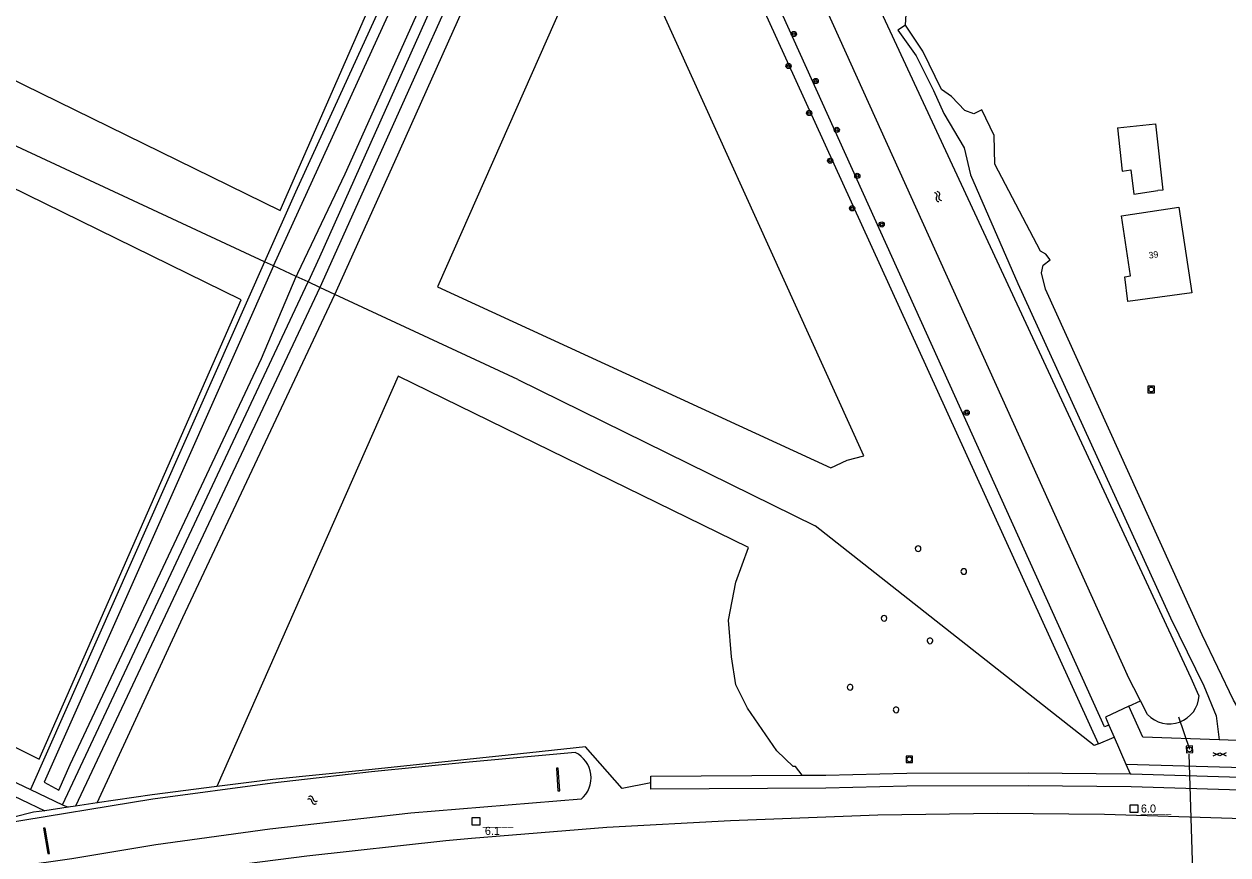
# Model space of a CAD drawing. Extents: x 133000 to 136000, y 400500 to 403500.
# Drawn here: x 133961.7 to 134147.3, y 401178.4 to 401306.4 of the extents above; entities that cross this region are included whole.
import ezdxf

# ---------------------------------------------------------------- set-up
doc = ezdxf.new("R2010")
doc.units = 0
for name, color, linetype in [('gg-afsc-hekwerk', 7, 'Continuous'), ('gg-anno-huisnummerreeks BGT', 7, 'Continuous'), ('gg-bbg-bijgebouw', 7, 'Continuous'), ('gg-bbg-gedigitaliseerde bebouwing', 7, 'Continuous'), ('gg-bbg-gedigitaliseerde bijgebouw', 7, 'Continuous'), ('gg-bbg-hoofdgebouw', 7, 'Continuous'), ('gg-bbg-hoogspanningsmast', 7, 'Continuous'), ('gg-knt-verharding', 7, 'Continuous'), ('gg-kntw-bovenkant insteek waterloop', 7, 'Continuous'), ('gg-kwrk-duiker nz buis', 7, 'Continuous'), ('gg-kwrk-kunstwerk', 7, 'Continuous'), ('gt-anno-nummer hm paal', 7, 'Continuous'), ('gt-grn-groengrens', 7, 'Continuous'), ('gt-grn-vlakafsluiter', 7, 'Continuous'), ('gt-symb-boom', 7, 'Continuous'), ('gt-symb-gesloten verharding', 7, 'Continuous'), ('gt-symb-hm paal', 7, 'Continuous'), ('gt-symb-rioolschacht', 7, 'Continuous'), ('gt-symb-watersymbool', 7, 'Continuous')]:
    doc.layers.add(name, color=color, linetype=linetype)

# ---------------------------------------------------------------- blocks, each defined once
blk = doc.blocks.new('gt0-RS')
at = {"layer": 'gt-symb-rioolschacht'}
blk.add_lwpolyline([(-0.5, -0.5), (0.5, -0.5), (0.5, 0.5), (-0.5, 0.5)], close=True, dxfattribs=at)
blk.add_circle((0, 0), 0.375, dxfattribs=at)
blk = doc.blocks.new('gt0-GESVH1')
at = {"layer": 'gt-symb-gesloten verharding'}
for p, q in [((-0.99, -0.26), (0.01, 0.24)), ((0.01, -0.26), (-0.99, 0.24)), ((0.01, 0.24), (1.01, -0.26)), ((1.01, 0.24), (0.01, -0.26))]:
    blk.add_line(p, q, dxfattribs=at)
blk = doc.blocks.new('gt0-BOOM')
at = {"layer": 'gt-symb-boom'}
for radius in [0.4, 0.2]:
    blk.add_circle((0, 0), radius, dxfattribs=at)
blk = doc.blocks.new('gt0-WA')
at = {"layer": 'gt-symb-watersymbool'}
for centre, start, end in [((-0.32, 0.02), 28.0725, 151.9275), ((0.43, 0.42), 208.0725, 331.9275), ((-0.32, -0.43), 28.0725, 151.9275), ((0.43, -0.03), 208.0725, 331.9275)]:
    blk.add_arc(centre, 0.425, start, end, dxfattribs=at)
blk = doc.blocks.new('gt0-HMpaal')
at = {"layer": 'gt-symb-hm paal'}
blk.add_lwpolyline([(-0.6, 0.6), (0.6, 0.6), (0.6, -0.6), (-0.6, -0.6)], close=True, dxfattribs=at)

msp = doc.modelspace()

# ---------------------------------------------------------------- linework, layer by layer
at = {"layer": 'gg-afsc-hekwerk'}
for p, q in [((133969.63, 401185.95), (133968.5, 401185.78)), ((133973, 401186.45), (133969.63, 401185.95)), ((133968.5, 401185.78), (133964.93, 401185.25))]:
    msp.add_line(p, q, dxfattribs=at)
for points in [[(134048.24, 401195.11), (134036.33, 401193.83), (134015.35, 401191.62), (134000.05, 401190.07), (133991.45, 401188.98)], [(134058.31, 401189.55), (134053.89, 401188.66), (134048.24, 401195.11)], [(133991.45, 401188.98), (133981.49, 401187.71), (133973, 401186.45)], [(133964.93, 401185.25), (133963.2, 401185), (133957.08, 401183.46)]]:
    msp.add_lwpolyline(points, dxfattribs=at)
at = {"layer": 'gg-bbg-bijgebouw'}
msp.add_lwpolyline([(134130.25, 401290.43), (134130.98, 401283.79), (134132.27, 401283.99), (134132.78, 401280.23), (134136.46, 401280.77)], dxfattribs=at)
at = {"layer": 'gg-bbg-gedigitaliseerde bebouwing'}
msp.add_lwpolyline([(134130.87, 401276.91), (134139.71, 401278.23), (134141.69, 401265.03), (134131.84, 401263.67)], dxfattribs=at)
at = {"layer": 'gg-bbg-gedigitaliseerde bijgebouw'}
msp.add_lwpolyline([(134130.25, 401290.43), (134136.12, 401291.07), (134137.24, 401280.86), (134136.46, 401280.77)], dxfattribs=at)
at = {"layer": 'gg-bbg-hoofdgebouw'}
msp.add_lwpolyline([(134131.84, 401263.67), (134131.36, 401267.52), (134132.26, 401267.65), (134130.87, 401276.91)], dxfattribs=at)
at = {"layer": 'gg-bbg-hoogspanningsmast'}
for centre, start, end in [((134099.51, 401225.63), 0, 180), ((134099.51, 401225.63), 180, 0), ((134106.55, 401222.1), 0, 180), ((134106.55, 401222.1), 180, 0), ((134094.26, 401214.89), 0, 180), ((134094.26, 401214.89), 180, 0), ((134101.34, 401211.41), 0.1332, 180.2656), ((134101.34, 401211.41), 180.2661, 0.1327), ((134089.03, 401204.27), 0.1332, 180.2656), ((134089.03, 401204.27), 180.2661, 0.1327), ((134096.11, 401200.78), 0.1327, 180.2661), ((134096.11, 401200.78), 180.2656, 0.1332)]:
    msp.add_arc(centre, 0.431, start, end, dxfattribs=at)
at = {"layer": 'gg-knt-verharding'}
for p, q in [((134128.92, 401198.42), (134129.74, 401196.56)), ((134129.74, 401196.56), (134131.54, 401192.42)), ((134152.86, 401195.92), (134145.91, 401196.16)), ((134131.54, 401192.42), (134152.8, 401191.81))]:
    msp.add_line(p, q, dxfattribs=at)
for points in [[(134097.58, 401306.29), (134096.38, 401305.49), (134099.2, 401301.54), (134101.86, 401296.21), (134103.48, 401292.66), (134106.59, 401287.38), (134107.59, 401283.19), (134114.87, 401266.48), (134138.4, 401214.98), (134143.52, 401204.5), (134145.43, 401199.87), (134145.91, 401196.16)], [(134152.86, 401195.92), (134150.48, 401198.29), (134148.1, 401202.3), (134143.3, 401212.36), (134119.14, 401265.57), (134118.55, 401268.13), (134118.76, 401269.27), (134119.85, 401270.1), (134119.18, 401270.99), (134118.39, 401271.43), (134111.35, 401284.83), (134111.23, 401289.28), (134109.35, 401293.24), (134108.08, 401292.59), (134106.72, 401293.11), (134104.66, 401295.27), (134103.1, 401296.34), (134100.24, 401302.25), (134097.58, 401306.29)], [(134131.97, 401201.34), (134128.38, 401199.66), (134128.92, 401198.42)], [(134145.91, 401196.16), (134134.14, 401196.56), (134131.97, 401201.34)], [(133846.84, 401144.85), (133876.76, 401153.5), (133898.49, 401159.1), (133919.96, 401164), (133941.47, 401168.4), (133963.14, 401172.3), (133983.98, 401175.59), (134005.29, 401178.31), (134026.74, 401180.66), (134030.7, 401181.03), (134051.53, 401182.71), (134070.59, 401183.72), (134093.28, 401184.63), (134111.76, 401184.85), (134128.22, 401184.7), (134147.89, 401184.12), (134156.18, 401183.82)]]:
    msp.add_lwpolyline(points, dxfattribs=at)
at = {"layer": 'gg-kntw-bovenkant insteek waterloop'}
for p, q in [((134141.58, 401205.66), (134075.06, 401348.61)), ((134068.77, 401345.42), (134131.73, 401206.19)), ((134133.79, 401202.19), (134131.73, 401206.19)), ((134142.8, 401203.01), (134141.58, 401205.66)), ((134134.87, 401200.09), (134133.79, 401202.19))]:
    msp.add_line(p, q, dxfattribs=at)
for points in [[(134046.68, 401194.2), (134029.74, 401192.7), (134015.25, 401191.25), (134000.03, 401189.5), (133981.58, 401187.03), (133958.42, 401183.24)], [(134047.57, 401187.03), (134021.33, 401184.85), (133999.62, 401182.43), (133982.02, 401180.01), (133969.11, 401177.84), (133960.75, 401176.67)]]:
    msp.add_lwpolyline(points, dxfattribs=at)
for centre, radius, start, end in [((134138.23, 401203.2), 4.58, 222.8427, 357.5789), ((134044.81, 401190.33), 4.3, 309.8861, 64.2754)]:
    msp.add_arc(centre, radius, start, end, dxfattribs=at)
at = {"layer": 'gg-kwrk-duiker nz buis'}
for p, q in [((134139.65, 401199.69), (134141.33, 401194.71)), ((134141.24, 401193.98), (134142.44, 401155.61))]:
    msp.add_line(p, q, dxfattribs=at)
at = {"layer": 'gg-kwrk-kunstwerk'}
for p, q in [((134058.31, 401190.55), (134081.62, 401190.7)), ((134058.31, 401189.55), (134058.31, 401190.55))]:
    msp.add_line(p, q, dxfattribs=at)
for points in [[(134044.01, 401188.3), (134044.27, 401188.32), (134044.05, 401191.81), (134043.8, 401191.8), (134044.01, 401188.3)], [(134081.62, 401190.7), (134085.3, 401190.72), (134097.78, 401191.01), (134116.49, 401191.09), (134132.19, 401190.93)], [(134132.19, 401190.93), (134132.35, 401190.93), (134154.21, 401190.28), (134191.91, 401188.24), (134196.02, 401189.38)], [(134196.96, 401187.65), (134191.91, 401186.24), (134154.21, 401188.28), (134132.35, 401188.93), (134116.49, 401189.09), (134097.78, 401189.01), (134085.3, 401188.72), (134058.31, 401188.55), (134058.31, 401189.55)], [(133964.97, 401182.57), (133964.72, 401182.54), (133965.39, 401178.66), (133965.63, 401178.68), (133964.97, 401182.57)]]:
    msp.add_lwpolyline(points, dxfattribs=at)
at = {"layer": 'gt-grn-groengrens'}
for p, q in [((134127.31, 401195.57), (134057.34, 401348.94)), ((133998.8, 401269.83), (133921.76, 401305.65)), ((133998.8, 401269.83), (133962.7, 401188.52)), ((134000.17, 401269.19), (133998.8, 401269.83)), ((134003.65, 401267.57), (134000.17, 401269.19)), ((134005.49, 401266.71), (134003.65, 401267.57)), ((133967.67, 401186.18), (134005.49, 401266.71)), ((134007.32, 401265.86), (133969.63, 401185.95)), ((134007.32, 401265.86), (134005.49, 401266.71)), ((134009.62, 401264.79), (134007.32, 401265.86)), ((134037.82, 401251.68), (134009.62, 401264.79)), ((134037.82, 401251.68), (134083.62, 401229.15)), ((134103, 401213.91), (134083.62, 401229.15)), ((133885.56, 401224.96), (133962.7, 401188.52)), ((133884.74, 401223.14), (133964.93, 401185.25)), ((134127.31, 401195.57), (134129.74, 401196.56)), ((133962.7, 401188.52), (133967.67, 401186.18)), ((133967.67, 401186.18), (133968.5, 401185.78))]:
    msp.add_line(p, q, dxfattribs=at)
for points in [[(133935.23, 401309.99), (134001.18, 401277.71), (134034.31, 401353.3), (133967.94, 401383.8), (133935.23, 401309.99)], [(134128.92, 401198.42), (134128.22, 401198.16), (134057.35, 401354.93), (134055.58, 401358.84)], [(134053.02, 401358.43), (134041.12, 401353.19), (134035.75, 401349.71), (134034.48, 401348.03), (134032.46, 401343.76), (134003.56, 401280.56), (133998.8, 401269.83)], [(134000.17, 401269.19), (134035.95, 401347.49), (134036.39, 401348.31), (134041.76, 401351.82), (134053.66, 401357.02)], [(134054.8, 401354.52), (134051.32, 401352.64), (134043.34, 401348.24), (134039.69, 401346.08), (134039.17, 401345.55), (134011.16, 401283.3), (134003.85, 401268.01), (134003.65, 401267.57)], [(134055.42, 401353.17), (134044.14, 401347.19), (134040.55, 401344.73), (134038.86, 401340.77), (134029.02, 401319.21), (134007.27, 401270.51), (134005.49, 401266.71)], [(134056.27, 401351.29), (134042.07, 401343.15), (134007.32, 401265.86)], [(134009.62, 401264.79), (134018.89, 401285.28), (134039.25, 401330.84), (134044.05, 401341.39), (134057.34, 401348.94)], [(134025.46, 401265.93), (134086.06, 401238.08), (134088.59, 401239.23), (134091.17, 401239.9), (134052.05, 401326.12), (134025.46, 401265.93)], [(133964.06, 401193.2), (133995.16, 401263.97), (133929.15, 401296.28), (133898.16, 401226.29), (133964.06, 401193.2)], [(134000.17, 401269.19), (133996.57, 401261.1), (133964.8, 401189.64), (133967.07, 401188.44), (133968.85, 401192.35), (133998.3, 401254.91), (134003.65, 401267.57)], [(133973, 401186.45), (133986.19, 401215.01), (134009.62, 401264.79)], [(134081.62, 401190.7), (134080.59, 401192.04), (134080.25, 401192.04), (134077.74, 401194.49), (134073.23, 401201.04), (134071.42, 401204.66), (134070.74, 401208.95), (134070.29, 401214.6), (134071.42, 401220.47), (134073.35, 401225.8), (134019.4, 401252.21), (133991.45, 401188.98)], [(134127.31, 401195.57), (134126.64, 401195.31), (134103, 401213.91)]]:
    msp.add_lwpolyline(points, dxfattribs=at)
at = {"layer": 'gt-grn-vlakafsluiter'}
for p, q in [((134097.58, 401306.29), (134098.16, 401316.86)), ((134131.97, 401201.34), (134133.79, 401202.19)), ((134131.54, 401192.42), (134132.19, 401190.93))]:
    msp.add_line(p, q, dxfattribs=at)

# ---------------------------------------------------------------- block references
at = {"layer": 'gt-symb-boom'}
for p in [(134080.36, 401304.9), (134079.54, 401299.97), (134083.73, 401297.67), (134082.72, 401292.73), (134086.97, 401290.13), (134085.97, 401285.38), (134090.14, 401283.05), (134089.34, 401278.05), (134093.9, 401275.56), (134107, 401246.57)]:
    msp.add_blockref('gt0-BOOM', p, dxfattribs=at)
at = {"layer": 'gt-symb-gesloten verharding'}
msp.add_blockref('gt0-GESVH1', (134145.98, 401193.95), dxfattribs=at)
at = {"layer": 'gt-symb-hm paal'}
for p in [(134132.77, 401185.57), (134031.37, 401183.62)]:
    msp.add_blockref('gt0-HMpaal', p, dxfattribs=at)
at = {"layer": 'gt-symb-rioolschacht'}
for p in [(134135.44, 401250.14), (134098.16, 401193.16)]:
    msp.add_blockref('gt0-RS', p, dxfattribs=at)
at = {"layer": 'gt-symb-rioolschacht', "rotation": -177.70709950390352}
msp.add_blockref('gt0-RS', (134141.33, 401194.71), dxfattribs=at)
at = {"layer": 'gt-symb-watersymbool'}
for p, rotation in [((134102.55, 401279.91), -64.8446275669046), ((134006.13, 401186.9), -24.131125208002)]:
    msp.add_blockref('gt0-WA', p, dxfattribs=dict(at, rotation=rotation))

# ---------------------------------------------------------------- texts
at = {"layer": 'gg-anno-huisnummerreeks BGT'}
msp.add_text('39', height=1, rotation=8.5, dxfattribs=at).set_placement((134135.12, 401270.29))
at = {"layer": 'gt-anno-nummer hm paal'}
for s, p in [('6.0', (134133.85, 401184.96)), ('6.1', (134032.74, 401181.51))]:
    msp.add_text(s, height=1.25, dxfattribs=at).set_placement(p)
at = {"layer": 'gt-symb-hm paal'}
for p in [(134133.85, 401184.96), (134032.45, 401183.01)]:
    msp.add_text('_____', height=1.25, dxfattribs=at).set_placement(p)

doc.saveas('drawing.dxf')
